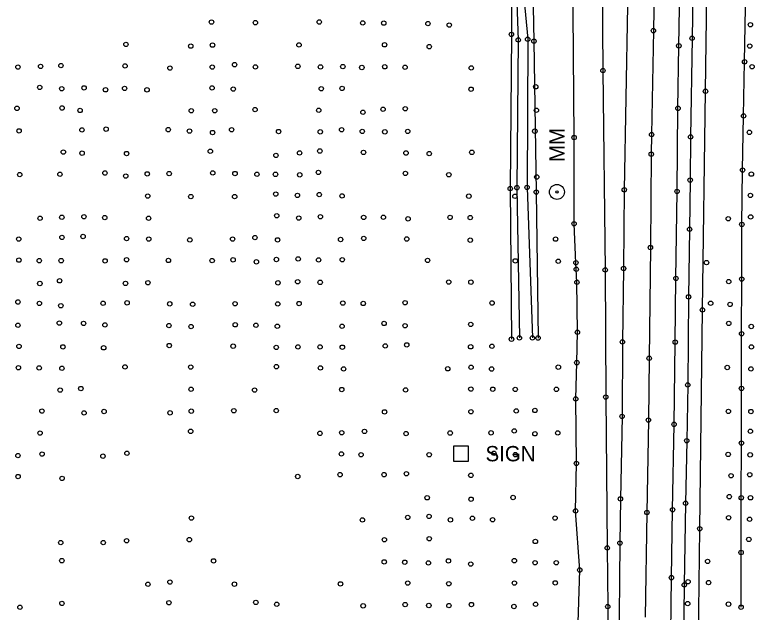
# Model space of a CAD drawing. Extents: x 20503438 to 20508873, y 7964251 to 7984667.
# Drawn here: x 20506321.9 to 20506660.6, y 7968929.7 to 7969202.7 of the extents above; entities that cross this region are included whole.
import ezdxf

# ---------------------------------------------------------------- set-up
doc = ezdxf.new("R2010")
doc.units = 0
for name, color, linetype in [('SurBreakLine', 7, 'Continuous'), ('SurConcreteSlab', 7, 'Continuous'), ('SurDrainageArrowDown', 7, 'Continuous'), ('SurDrainageArrowUp', 7, 'Continuous'), ('SurEdgeRoadPaved', 7, 'Continuous'), ('SurEdgeShoulderPaved', 7, 'Continuous'), ('SurGuardRailCable', 7, 'Continuous'), ('SurPointsNonDTM', 7, 'Continuous'), ('SurRoadPoints', 7, 'Continuous'), ('SurSurveyPoints', 7, 'Continuous')]:
    doc.layers.add(name, color=color, linetype=linetype)

msp = doc.modelspace()

# ---------------------------------------------------------------- linework, layer by layer
at = {"layer": 'SurBreakLine'}
for points in [[(20506618.14, 7969523.36), (20506617.67, 7969481.03), (20506617.43, 7969457.83), (20506616.96, 7969412.61), (20506616.41, 7969374.63), (20506615.97, 7969343.84), (20506615.38, 7969298.61), (20506613.68, 7969195.48), (20506612.84, 7969147.98), (20506612.67, 7969139.02), (20506612.29, 7969096.34), (20506611.74, 7969045.72), (20506611.38, 7969017.5), (20506610.7, 7968975.24), (20506609.9, 7968927.43)], [(20506530.55, 7969501.87), (20506539.77, 7969458.14), (20506549.36, 7969373.83), (20506553.86, 7969325.71), (20506557.91, 7969281.18), (20506558.28, 7969230.17), (20506559.1, 7969190.68), (20506560.16, 7969121.72), (20506560.98, 7969054.99)], [(20506518.36, 7969500.09), (20506526.15, 7969455.03), (20506538.74, 7969371.16), (20506542.8, 7969324.25), (20506544.83, 7969280.33), (20506548.66, 7969228.93), (20506548.82, 7969193.76), (20506548.24, 7969123.29), (20506548.83, 7969054.45)], [(20506526.38, 7969501.4), (20506535.77, 7969458.35), (20506545.25, 7969373.27), (20506550.88, 7969325.87), (20506553.23, 7969281.58), (20506552.68, 7969229.8), (20506556.22, 7969191.53), (20506555.93, 7969123.81), (20506558.38, 7969055.03)]]:
    msp.add_lwpolyline(points, dxfattribs=at)
at = {"layer": 'SurConcreteSlab'}
msp.add_lwpolyline([(20506564.49, 7969514.44), (20506574.01, 7969461.11), (20506578.45, 7969434.44), (20506583.17, 7969394.51), (20506586.51, 7969354.44), (20506588.8, 7969317.85), (20506589.77, 7969274.23), (20506590.63, 7969177.23), (20506591.64, 7969086.12), (20506591.92, 7969027.98), (20506592.58, 7968959.05), (20506592.8, 7968932.21), (20506593.59, 7968825.07), (20506593.73, 7968776.04), (20506594.33, 7968740.28), (20506595.27, 7968683.67)], dxfattribs=at)
at = {"layer": 'SurDrainageArrowDown'}
msp.add_lwpolyline([(20506653.71, 7968931.94), (20506653.76, 7968956.94), (20506653.81, 7968981.94), (20506653.87, 7969006.94), (20506653.92, 7969031.94), (20506653.97, 7969056.94), (20506654.02, 7969081.94), (20506654.08, 7969106.94), (20506654.43, 7969131.75), (20506654.89, 7969156.5), (20506655.35, 7969181.25), (20506655.81, 7969206), (20506656.26, 7969230.74), (20506656.72, 7969255.49), (20506657.18, 7969280.24), (20506657.62, 7969305), (20506658, 7969329.78), (20506658.38, 7969354.56), (20506658.75, 7969379.34), (20506659.13, 7969404.12), (20506659.51, 7969428.89), (20506659.89, 7969453.67), (20506660.27, 7969478.45), (20506660.63, 7969503.23)], dxfattribs=at)
at = {"layer": 'SurDrainageArrowUp'}
msp.add_lwpolyline([(20506438.1, 7969771.83), (20506443.35, 7969742.94), (20506462.68, 7969706.4), (20506478.32, 7969662.6), (20506496.28, 7969609.97), (20506512.32, 7969564.26), (20506521.33, 7969501.72), (20506530.41, 7969455.42), (20506542.25, 7969371.11), (20506545.39, 7969325.12), (20506547.61, 7969281.18), (20506550.51, 7969229.55), (20506551.89, 7969191.24), (20506551.28, 7969123.71), (20506552.43, 7969055.04)], dxfattribs=at)
at = {"layer": 'SurEdgeRoadPaved'}
for points in [[(20506621.49, 7968907.38), (20506621.92, 7968945.44), (20506622.44, 7968976.48), (20506623.13, 7969015.52), (20506623.63, 7969053.1), (20506623.96, 7969082.25), (20506624.47, 7969121.99), (20506624.91, 7969159.97), (20506625.3, 7969188.54), (20506625.87, 7969223.35), (20506626.51, 7969255.54), (20506627.28, 7969310.85), (20506627.6, 7969331.39), (20506628.32, 7969376.84), (20506628.68, 7969403.15), (20506629.02, 7969437.79), (20506629.57, 7969489.48)], [(20506595.72, 7969487.19), (20506595.11, 7969466.36), (20506594.59, 7969424.65), (20506594.85, 7969394.48), (20506596.15, 7969383.03), (20506600.49, 7969326.21), (20506603.4, 7969291.1), (20506600.36, 7969122.74), (20506600.06, 7969086.76), (20506599.49, 7969053.21), (20506599.36, 7969019.14), (20506598.62, 7968981.46), (20506598.4, 7968961.23), (20506597.81, 7968911.23), (20506596.74, 7968813.5), (20506596.12, 7968772.39), (20506595.63, 7968706.72), (20506595.11, 7968672.96), (20506595.06, 7968637.97), (20506594.54, 7968602.04), (20506594.11, 7968535.15), (20506593.63, 7968499.17)]]:
    msp.add_lwpolyline(points, dxfattribs=at)
at = {"layer": 'SurEdgeShoulderPaved'}
for points in [[(20506579.21, 7968920.08), (20506580.04, 7968948.94), (20506578.13, 7968975.95), (20506578.51, 7968997.69), (20506578.2, 7969027.13), (20506578.68, 7969043.72), (20506578.97, 7969057.63), (20506578.72, 7969080.47), (20506578.43, 7969086.41), (20506578.28, 7969089.38), (20506577.4, 7969107.2), (20506577.45, 7969146.63), (20506576.88, 7969223.07), (20506576.47, 7969254.43), (20506575.66, 7969311.26), (20506574.14, 7969339.42), (20506569.62, 7969394.88), (20506566.46, 7969422.38), (20506563.2, 7969444.91), (20506558.41, 7969475.22), (20506553.3, 7969503.59)], [(20506635.48, 7969504.27), (20506635.15, 7969461.94), (20506634.88, 7969430.9), (20506634.45, 7969402.36), (20506634.07, 7969371.62), (20506633.61, 7969329.61), (20506633.23, 7969307.1), (20506632.49, 7969262.27), (20506631.93, 7969231.4), (20506631.34, 7969191.98), (20506630.67, 7969146.89), (20506630.47, 7969127.19), (20506630.23, 7969104.68), (20506629.72, 7969073.79), (20506629.37, 7969033.53), (20506628.89, 7969008.02), (20506628.37, 7968979.45), (20506627.76, 7968942.11), (20506627.2, 7968902.1)]]:
    msp.add_lwpolyline(points, dxfattribs=at)
at = {"layer": 'SurGuardRailCable'}
msp.add_lwpolyline([(20506628.76, 7968467.84), (20506630.09, 7968567.83), (20506631.3, 7968667.82), (20506632.48, 7968767.82), (20506633.65, 7968867.81), (20506634.84, 7968967.8), (20506636.09, 7969067.8), (20506637.47, 7969167.79), (20506638.85, 7969267.78), (20506639.32, 7969301.82)], dxfattribs=at)
at = {"layer": 'SurPointsNonDTM'}
for centre in [(20506637.47, 7969167.79), (20506636.09, 7969067.8), (20506634.84, 7968967.8)]:
    msp.add_circle(centre, 1, dxfattribs=at)
at = {"layer": 'SurRoadPoints'}
msp.add_lwpolyline([(20506525.75, 7968998.69), (20506525.75, 7968998.69), (20506529.18, 7968998.69), (20506529.18, 7969005.55), (20506522.32, 7969005.55), (20506522.32, 7968998.69), (20506525.75, 7968998.69)], dxfattribs=at)
for radius in [3.43, 0.571]:
    msp.add_circle((20506569.61, 7969121.75), radius, dxfattribs=at)
at = {"layer": 'SurSurveyPoints'}
for centre in [(20506411.76, 7969199.42), (20506431.8, 7969199.13), (20506460.98, 7969199.44), (20506480.84, 7969199.02), (20506490.48, 7969198.92), (20506510.65, 7969198.71), (20506520.37, 7969198.04), (20506658.02, 7969198.2), (20506548.82, 7969193.76), (20506613.68, 7969195.48), (20506372.68, 7969189.21), (20506451.74, 7969188.97), (20506490.82, 7969189.02), (20506551.89, 7969191.24), (20506556.22, 7969191.53), (20506559.1, 7969190.68), (20506631.34, 7969191.98), (20506402.3, 7969188.41), (20506412.21, 7969188.86), (20506511.23, 7969188.16), (20506625.3, 7969188.54), (20506657.7, 7969188.42), (20506323.31, 7969178.82), (20506333.65, 7969179.13), (20506342.96, 7969179.51), (20506372.25, 7969179.34), (20506412.09, 7969178.82), (20506422.28, 7969179.93), (20506431.81, 7969178.92), (20506451.2, 7969179.17), (20506461.56, 7969178.88), (20506471.76, 7969179.03), (20506490.91, 7969178.96), (20506655.35, 7969181.25), (20506658.75, 7969178.97), (20506392.78, 7969178.4), (20506480.44, 7969178.64), (20506500.21, 7969178.75), (20506530.45, 7969178.42), (20506590.63, 7969177.23), (20506333.29, 7969169.53), (20506343.31, 7969168.92), (20506353.53, 7969169.33), (20506372.07, 7969169.08), (20506412.02, 7969169.28), (20506421.71, 7969168.76), (20506461.93, 7969168.93), (20506471.44, 7969169.08), (20506530.36, 7969168.72), (20506559.9, 7969169.82), (20506363.33, 7969168.45), (20506382.29, 7969168.44), (20506322.89, 7969159.98), (20506343.5, 7969160.13), (20506351.68, 7969159), (20506402.52, 7969158.88), (20506413.21, 7969158.89), (20506431.64, 7969159.38), (20506460.74, 7969159.1), (20506490.14, 7969159.53), (20506500.3, 7969159.77), (20506560.23, 7969159.07), (20506624.91, 7969159.97), (20506480.93, 7969158.18), (20506654.89, 7969156.5), (20506323.81, 7969149.67), (20506352.57, 7969150.11), (20506363.61, 7969150.46), (20506391.97, 7969150.22), (20506401.7, 7969149.58), (20506412.23, 7969148.91), (20506420.96, 7969150.17), (20506442.42, 7969149.37), (20506461.46, 7969149.24), (20506471.22, 7969150.18), (20506480.65, 7969149.45), (20506490.96, 7969149.24), (20506501.42, 7969149.43), (20506559.49, 7969149.54), (20506657.55, 7969149), (20506577.45, 7969146.63), (20506612.84, 7969147.98), (20506630.67, 7969146.89), (20506344.06, 7969140), (20506352.64, 7969139.48), (20506372.95, 7969139.31), (20506411.22, 7969140.35), (20506441.21, 7969138.47), (20506451.98, 7969139.61), (20506461.26, 7969140.47), (20506481.21, 7969139.85), (20506500.63, 7969139.56), (20506511.23, 7969139.27), (20506530.71, 7969139.86), (20506612.67, 7969139.02), (20506654.43, 7969131.75), (20506324.12, 7969129.66), (20506342.48, 7969129.83), (20506363.07, 7969130.41), (20506372.6, 7969129), (20506382.41, 7969130.02), (20506392.41, 7969130.15), (20506412.35, 7969130.46), (20506422.49, 7969130.17), (20506432.53, 7969129.82), (20506441, 7969129.8), (20506452.09, 7969129.57), (20506460.61, 7969130.67), (20506500.36, 7969130.25), (20506520.2, 7969129.64), (20506560.35, 7969128.58), (20506658.42, 7969129.9), (20506630.47, 7969127.19), (20506548.24, 7969123.29), (20506551.28, 7969123.71), (20506555.93, 7969123.81), (20506560.16, 7969121.72), (20506600.36, 7969122.74), (20506624.47, 7969121.99), (20506382.61, 7969119.89), (20506402.31, 7969119.65), (20506422.34, 7969119.61), (20506441.13, 7969120.79), (20506451.03, 7969120.17), (20506461.01, 7969120.56), (20506471.44, 7969119.93), (20506529.34, 7969119.82), (20506550.37, 7969119.77), (20506658, 7969120.19), (20506333.43, 7969109.74), (20506343.37, 7969110.19), (20506353.47, 7969110.41), (20506363, 7969110.05), (20506383, 7969109.72), (20506441.58, 7969110.86), (20506451.65, 7969109.79), (20506461.51, 7969110.4), (20506481.28, 7969110.14), (20506490.31, 7969110.19), (20506501.59, 7969109.47), (20506520.79, 7969110.1), (20506529.96, 7969110.05), (20506647.9, 7969109.49), (20506658.11, 7969110.32), (20506577.4, 7969107.2), (20506630.23, 7969104.68), (20506654.08, 7969106.94), (20506343.41, 7969100.99), (20506353.05, 7969101.39), (20506323.66, 7969100.22), (20506372.95, 7969100.44), (20506383.11, 7969100.23), (20506401.86, 7969099.8), (20506421.4, 7969100.22), (20506431.61, 7969100.87), (20506441.96, 7969099.85), (20506470.75, 7969100.01), (20506481.33, 7969100.52), (20506500.95, 7969100.24), (20506529.97, 7969099.71), (20506568.96, 7969100.19), (20506612.29, 7969096.34), (20506372.93, 7969090.77), (20506441.39, 7969090.88), (20506451.36, 7969091.12), (20506471.49, 7969090.77), (20506323.74, 7969090.59), (20506333.04, 7969090.34), (20506343.07, 7969090.34), (20506363.13, 7969090.25), (20506392.04, 7969090.43), (20506412.05, 7969090.39), (20506421.64, 7969090.72), (20506432.25, 7969089.8), (20506460.68, 7969090.69), (20506510.51, 7969090.45), (20506550.59, 7969090.25), (20506570.18, 7969090.05), (20506578.28, 7969089.38), (20506637.94, 7969089.46), (20506578.43, 7969086.41), (20506591.64, 7969086.12), (20506600.06, 7969086.76), (20506342.35, 7969081.14), (20506451.13, 7969080.72), (20506520.15, 7969080.57), (20506623.96, 7969082.25), (20506648.07, 7969080.77), (20506654.02, 7969081.94), (20506333.32, 7969079.91), (20506372.46, 7969079.95), (20506382.68, 7969080.26), (20506442.13, 7969080.21), (20506461.4, 7969080.44), (20506530.27, 7969080.51), (20506578.72, 7969080.47), (20506629.72, 7969073.79), (20506323.28, 7969071.45), (20506333.13, 7969070.82), (20506362.24, 7969070.85), (20506373.2, 7969071.06), (20506392.68, 7969070.6), (20506403.15, 7969070.41), (20506422.51, 7969070.64), (20506442, 7969070.54), (20506451.79, 7969070.74), (20506471.77, 7969070.96), (20506481.08, 7969070.78), (20506500.23, 7969071.12), (20506539.98, 7969070.99), (20506639.83, 7969070.86), (20506342.91, 7969069.73), (20506648.73, 7969070.33), (20506323.3, 7969060.8), (20506342.23, 7969061.81), (20506353.28, 7969061.68), (20506363.05, 7969060.97), (20506392.29, 7969060.65), (20506422.59, 7969061.02), (20506432.08, 7969060.8), (20506441.83, 7969060.34), (20506471.41, 7969060.34), (20506490.62, 7969061.63), (20506500.22, 7969060.58), (20506530.22, 7969061.2), (20506648.12, 7969061.67), (20506658.41, 7969060.25), (20506402.42, 7969060.21), (20506578.97, 7969057.63), (20506653.97, 7969056.94), (20506548.83, 7969054.45), (20506552.43, 7969055.04), (20506558.38, 7969055.03), (20506560.98, 7969054.99), (20506323.79, 7969051.17), (20506343.87, 7969050.94), (20506362.48, 7969050.51), (20506392.44, 7969051.55), (20506421.65, 7969051.26), (20506441.34, 7969050.68), (20506451.26, 7969050.91), (20506461.35, 7969050.89), (20506471.54, 7969050.78), (20506491.13, 7969051.38), (20506500.98, 7969051.85), (20506530.18, 7969050.97), (20506539.89, 7969051.2), (20506599.49, 7969053.21), (20506623.63, 7969053.1), (20506658.45, 7969050.91), (20506578.68, 7969043.72), (20506611.74, 7969045.72), (20506323.55, 7969041.38), (20506333.01, 7969041.31), (20506343.39, 7969041.17), (20506372.23, 7969041.77), (20506402.27, 7969041.72), (20506441.42, 7969041.88), (20506461.54, 7969041.33), (20506472.12, 7969040.87), (20506519.69, 7969040.91), (20506530.35, 7969041.59), (20506539.73, 7969040.82), (20506570.23, 7969041.66), (20506647.42, 7969041.5), (20506658.23, 7969040.83), (20506629.37, 7969033.53), (20506342.6, 7969031.19), (20506352.06, 7969031.89), (20506402.43, 7969031.56), (20506431.46, 7969031.17), (20506471.28, 7969031.43), (20506500.45, 7969031.27), (20506530.26, 7969031.65), (20506540.25, 7969031.59), (20506550.56, 7969031.5), (20506569.35, 7969031.52), (20506653.92, 7969031.94), (20506578.2, 7969027.13), (20506591.92, 7969027.98), (20506334.25, 7969021.61), (20506353.52, 7969020.74), (20506362.66, 7969021.39), (20506392.81, 7969020.79), (20506402.52, 7969021.55), (20506421.96, 7969021.72), (20506441.35, 7969021.8), (20506490.82, 7969021.22), (20506530.28, 7969021.27), (20506551.03, 7969021.65), (20506559.55, 7969021.86), (20506647.96, 7969021.42), (20506658.24, 7969021.38), (20506599.36, 7969019.14), (20506611.38, 7969017.5), (20506623.13, 7969015.52), (20506333.44, 7969011.54), (20506402.24, 7969012.33), (20506461.31, 7969011.41), (20506471.25, 7969011.7), (20506481.66, 7969012.3), (20506500.65, 7969011.27), (20506520.8, 7969011.56), (20506539.52, 7969011.64), (20506550.08, 7969012.52), (20506559.54, 7969011.2), (20506569.99, 7969011.59), (20506657.97, 7969012.36), (20506628.89, 7969008.02), (20506653.87, 7969006.94), (20506323.29, 7969001.24), (20506334.37, 7969001.92), (20506362.13, 7969000.98), (20506373.12, 7969002.29), (20506471.12, 7969002.01), (20506480.12, 7969001.65), (20506511.21, 7969001.64), (20506540.78, 7969002.29), (20506550.62, 7969001.66), (20506647.83, 7969001.76), (20506657.88, 7969001.58), (20506578.51, 7968997.69), (20506470.49, 7968992.52), (20506490.64, 7968992.52), (20506500.8, 7968992.96), (20506323.37, 7968991.66), (20506343.51, 7968990.83), (20506451.14, 7968991.68), (20506530.26, 7968992.21), (20506649.15, 7968992.05), (20506657.72, 7968992.47), (20506648.35, 7968982.46), (20506510.3, 7968981.95), (20506530.36, 7968981.3), (20506549.53, 7968982.08), (20506598.62, 7968981.46), (20506628.37, 7968979.45), (20506653.81, 7968981.94), (20506658.04, 7968981.94), (20506578.13, 7968975.95), (20506622.44, 7968976.48), (20506402.55, 7968972.67), (20506501.43, 7968972.97), (20506511.17, 7968973.44), (20506530.96, 7968972.58), (20506568.72, 7968972.7), (20506610.7, 7968975.24), (20506648.03, 7968972.84), (20506480.73, 7968971.85), (20506520.94, 7968971.88), (20506540.2, 7968971.92), (20506657.62, 7968972.12), (20506372.98, 7968962.34), (20506401.62, 7968962.8), (20506490.76, 7968962.77), (20506511.23, 7968963.22), (20506657.28, 7968962.95), (20506342.85, 7968961.46), (20506362.31, 7968961.45), (20506559.73, 7968961.98), (20506592.58, 7968959.05), (20506598.4, 7968961.23), (20506653.76, 7968956.94), (20506343.37, 7968953.21), (20506412.73, 7968953.11), (20506490.67, 7968952.66), (20506500.03, 7968952.51), (20506510.85, 7968952.17), (20506520.03, 7968953.11), (20506550.12, 7968953.2), (20506559.59, 7968952.25), (20506569.27, 7968952.25), (20506638.45, 7968952.89), (20506530.22, 7968951.63), (20506580.04, 7968948.94), (20506621.92, 7968945.44), (20506382.71, 7968942.44), (20506392.74, 7968943.43), (20506422.25, 7968942.47), (20506470.69, 7968942.6), (20506501.43, 7968942.96), (20506520.19, 7968942.64), (20506550.17, 7968942.95), (20506568.81, 7968943.06), (20506627.76, 7968942.11), (20506629.52, 7968943.6), (20506638.86, 7968943.19), (20506324.2, 7968931.89), (20506343.39, 7968933.66), (20506392.28, 7968933.97), (20506432.01, 7968934.15), (20506441.54, 7968933.29), (20506481.05, 7968932.56), (20506500.25, 7968933.11), (20506511.06, 7968932.72), (20506520.22, 7968932.69), (20506530.49, 7968933.15), (20506549.95, 7968932.25), (20506559.85, 7968933.29), (20506592.8, 7968932.21), (20506629.33, 7968933.59), (20506647.98, 7968933.33), (20506653.71, 7968931.94)]:
    msp.add_circle(centre, 1, dxfattribs=at)

# ---------------------------------------------------------------- texts
at = {"layer": 'SurRoadPoints'}
for s, rotation, p in [('MM', 90, (20506573.11, 7969135.46)), ('SIGN', 360, (20506536.96, 7968998.62))]:
    msp.add_text(s, height=6.995, rotation=rotation, dxfattribs=at).set_placement(p)

doc.saveas('drawing.dxf')
